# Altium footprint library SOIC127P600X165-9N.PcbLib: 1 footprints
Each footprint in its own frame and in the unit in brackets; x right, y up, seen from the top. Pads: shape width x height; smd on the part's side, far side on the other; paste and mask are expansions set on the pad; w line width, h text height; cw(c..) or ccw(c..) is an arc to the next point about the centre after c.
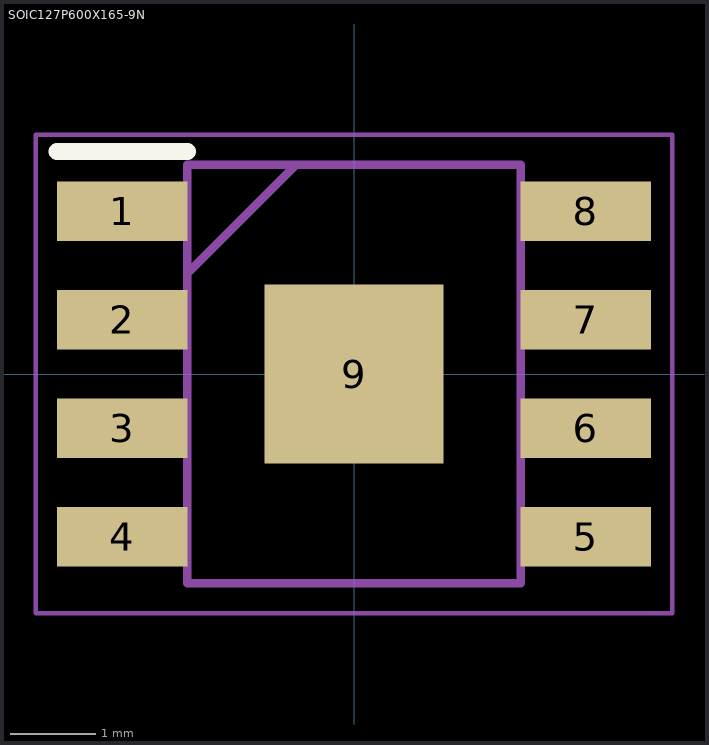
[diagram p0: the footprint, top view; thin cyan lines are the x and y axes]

## SOIC127P600X165-9N [mm]
pads (9):
  rect 1.525x0.7 smd: 1(-2.712,1.905) 2(-2.712,0.635) 3(-2.712,-0.635) 4(-2.712,-1.905) 5(2.712,-1.905) 6(2.712,-0.635) 7(2.712,0.635) 8(2.712,1.905)
  rect 2.09x2.09 smd: 9(0,0)
Top Overlay:
  lines w0.2: -3.475,2.605 -1.95,2.605
Mechanical 15:
  lines w0.1: -1.95,1.18 -0.68,2.45 ; -1.95,-2.45 1.95,-2.45 1.95,2.45 -1.95,2.45 -1.95,-2.45
Mechanical 20:
  lines w0.05: -3.725,-2.8 3.725,-2.8 3.725,2.8 -3.725,2.8 -3.725,-2.8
